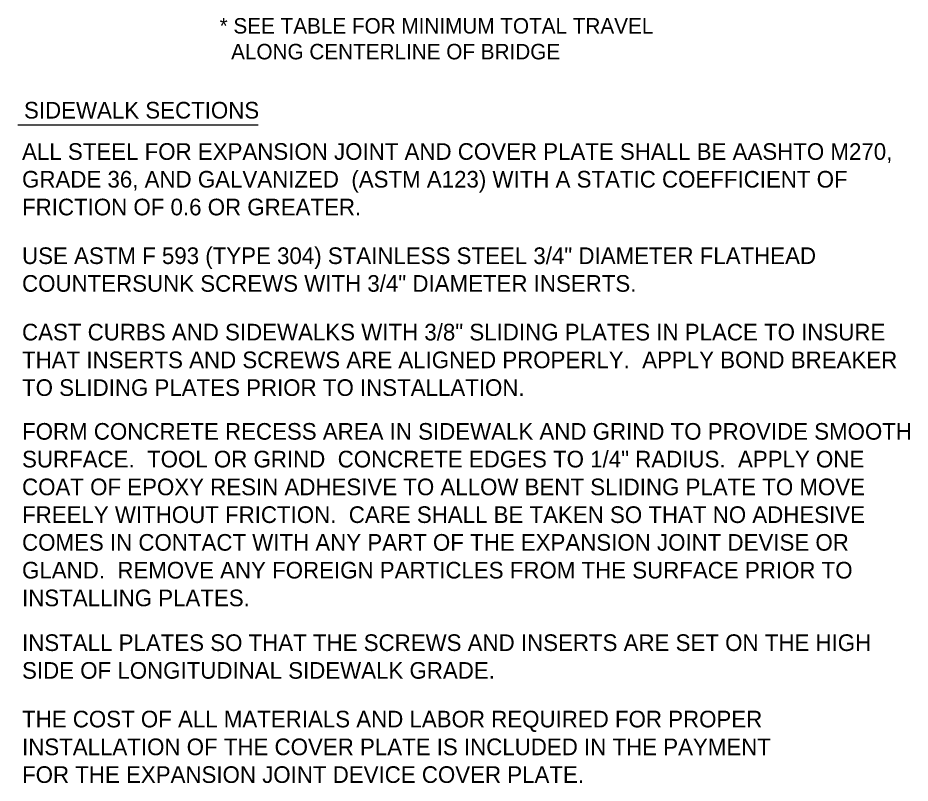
# Model space of a CAD drawing. Extents: x 19590 to 20151, y 19944 to 20103.
# Drawn here: x 19680.5 to 19707.15, y 20018.9 to 20041.77 of the extents above; entities that cross this region are included whole.
import ezdxf

# ---------------------------------------------------------------- set-up
doc = ezdxf.new("R2010")
doc.units = 0
doc.layers.add('DETAIL_TEXT_DIMEN_PR', color=7, linetype='Continuous')

msp = doc.modelspace()

# ---------------------------------------------------------------- linework, layer by layer
at = {"layer": 'DETAIL_TEXT_DIMEN_PR'}
msp.add_line((19680.499, 20038.565), (19687.681, 20038.565), dxfattribs=at)
msp.add_line((19680.499, 20038.565), (19687.681, 20038.565), dxfattribs=at)

# ---------------------------------------------------------------- texts
for s, height, p in [('* SEE TABLE FOR MINIMUM TOTAL TRAVEL ', 0.4625, (19686.526, 20041.296)), ('* SEE TABLE FOR MINIMUM TOTAL TRAVEL ', 0.4625, (19686.526, 20041.296)), ('  ALONG CENTERLINE OF BRIDGE', 0.4625, (19686.526, 20040.525)), ('  ALONG CENTERLINE OF BRIDGE', 0.4625, (19686.526, 20040.525)), ('ALL STEEL FOR EXPANSION JOINT AND COVER PLATE SHALL BE AASHTO M270, ', 0.4976, (19680.625, 20037.523)), ('ALL STEEL FOR EXPANSION JOINT AND COVER PLATE SHALL BE AASHTO M270, ', 0.4976, (19680.625, 20037.523)), ('GRADE 36, AND GALVANIZED  (ASTM A123) WITH A STATIC COEFFICIENT OF ', 0.4976, (19680.625, 20036.694)), ('GRADE 36, AND GALVANIZED  (ASTM A123) WITH A STATIC COEFFICIENT OF ', 0.4976, (19680.625, 20036.694)), ('FRICTION OF 0.6 OR GREATER.', 0.4976, (19680.625, 20035.864)), ('FRICTION OF 0.6 OR GREATER.', 0.4976, (19680.625, 20035.864)), ('USE ASTM F 593 (TYPE 304) STAINLESS STEEL 3/4" DIAMETER FLATHEAD ', 0.4976, (19680.625, 20034.41)), ('USE ASTM F 593 (TYPE 304) STAINLESS STEEL 3/4" DIAMETER FLATHEAD ', 0.4976, (19680.625, 20034.41)), ('COUNTERSUNK SCREWS WITH 3/4" DIAMETER INSERTS.', 0.4976, (19680.625, 20033.581)), ('COUNTERSUNK SCREWS WITH 3/4" DIAMETER INSERTS.', 0.4976, (19680.625, 20033.581)), ('CAST CURBS AND SIDEWALKS WITH 3/8" SLIDING PLATES IN PLACE TO INSURE ', 0.4976, (19680.625, 20032.127)), ('CAST CURBS AND SIDEWALKS WITH 3/8" SLIDING PLATES IN PLACE TO INSURE ', 0.4976, (19680.625, 20032.127)), ('THAT INSERTS AND SCREWS ARE ALIGNED PROPERLY.  APPLY BOND BREAKER', 0.4976, (19680.625, 20031.298)), ('THAT INSERTS AND SCREWS ARE ALIGNED PROPERLY.  APPLY BOND BREAKER', 0.4976, (19680.625, 20031.298)), ('TO SLIDING PLATES PRIOR TO INSTALLATION.', 0.4976, (19680.625, 20030.469)), ('TO SLIDING PLATES PRIOR TO INSTALLATION.', 0.4976, (19680.625, 20030.469)), ('FORM CONCRETE RECESS AREA IN SIDEWALK AND GRIND TO PROVIDE SMOOTH ', 0.4976, (19680.625, 20029.161)), ('FORM CONCRETE RECESS AREA IN SIDEWALK AND GRIND TO PROVIDE SMOOTH ', 0.4976, (19680.625, 20029.161)), ('SURFACE.  TOOL OR GRIND  CONCRETE EDGES TO 1/4" RADIUS.  APPLY ONE ', 0.4976, (19680.625, 20028.332)), ('SURFACE.  TOOL OR GRIND  CONCRETE EDGES TO 1/4" RADIUS.  APPLY ONE ', 0.4976, (19680.625, 20028.332)), ('COAT OF EPOXY RESIN ADHESIVE TO ALLOW BENT SLIDING PLATE TO MOVE ', 0.4976, (19680.625, 20027.502)), ('COAT OF EPOXY RESIN ADHESIVE TO ALLOW BENT SLIDING PLATE TO MOVE ', 0.4976, (19680.625, 20027.502)), ('FREELY WITHOUT FRICTION.  CARE SHALL BE TAKEN SO THAT NO ADHESIVE ', 0.4976, (19680.625, 20026.673)), ('FREELY WITHOUT FRICTION.  CARE SHALL BE TAKEN SO THAT NO ADHESIVE ', 0.4976, (19680.625, 20026.673)), ('COMES IN CONTACT WITH ANY PART OF THE EXPANSION JOINT DEVISE OR ', 0.4976, (19680.625, 20025.844)), ('COMES IN CONTACT WITH ANY PART OF THE EXPANSION JOINT DEVISE OR ', 0.4976, (19680.625, 20025.844)), ('GLAND.  REMOVE ANY FOREIGN PARTICLES FROM THE SURFACE PRIOR TO ', 0.4976, (19680.625, 20025.014)), ('GLAND.  REMOVE ANY FOREIGN PARTICLES FROM THE SURFACE PRIOR TO ', 0.4976, (19680.625, 20025.014)), ('INSTALLING PLATES.', 0.4976, (19680.625, 20024.185)), ('INSTALLING PLATES.', 0.4976, (19680.625, 20024.185)), ('INSTALL PLATES SO THAT THE SCREWS AND INSERTS ARE SET ON THE HIGH ', 0.4976, (19680.625, 20022.848)), ('INSTALL PLATES SO THAT THE SCREWS AND INSERTS ARE SET ON THE HIGH ', 0.4976, (19680.625, 20022.848)), ('SIDE OF LONGITUDINAL SIDEWALK GRADE.', 0.4976, (19680.625, 20022.019)), ('SIDE OF LONGITUDINAL SIDEWALK GRADE.', 0.4976, (19680.625, 20022.019)), ('THE COST OF ALL MATERIALS AND LABOR REQUIRED FOR PROPER ', 0.4976, (19680.625, 20020.565)), ('THE COST OF ALL MATERIALS AND LABOR REQUIRED FOR PROPER ', 0.4976, (19680.625, 20020.565)), ('INSTALLATION OF THE COVER PLATE IS INCLUDED IN THE PAYMENT ', 0.4976, (19680.625, 20019.735)), ('INSTALLATION OF THE COVER PLATE IS INCLUDED IN THE PAYMENT ', 0.4976, (19680.625, 20019.735)), ('FOR THE EXPANSION JOINT DEVICE COVER PLATE.', 0.4976, (19680.625, 20018.906)), ('FOR THE EXPANSION JOINT DEVICE COVER PLATE.', 0.4976, (19680.625, 20018.906))]:
    msp.add_text(s, height=height, dxfattribs=at).set_placement(p)
msp.add_text('SIDEWALK SECTIONS', height=0.4976, rotation=0, dxfattribs=at).set_placement((19680.683, 20038.757))
msp.add_text('SIDEWALK SECTIONS', height=0.4976, rotation=0, dxfattribs=at).set_placement((19680.683, 20038.757))

doc.saveas('drawing.dxf')
